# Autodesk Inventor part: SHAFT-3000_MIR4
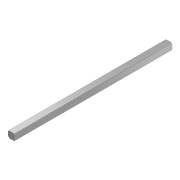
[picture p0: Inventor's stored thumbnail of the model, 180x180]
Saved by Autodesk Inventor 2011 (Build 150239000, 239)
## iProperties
Created: 2007-08
Part Number: SHAFT-3000_MIR4
Material: Stainless Steel
Document SubType Name: Modeling
Density: 8.08 g/cm^3
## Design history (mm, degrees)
derived "SHAFT-3000.ipt"
  workplane "Work Plane1"
  workplane "Work Plane2"
  workaxis "Work Axis1"
body "Solid1"
tag "TaggingFeature2"
feature "DerivedBody::SHAFT-3000.ipt" dims "d0" = 10
